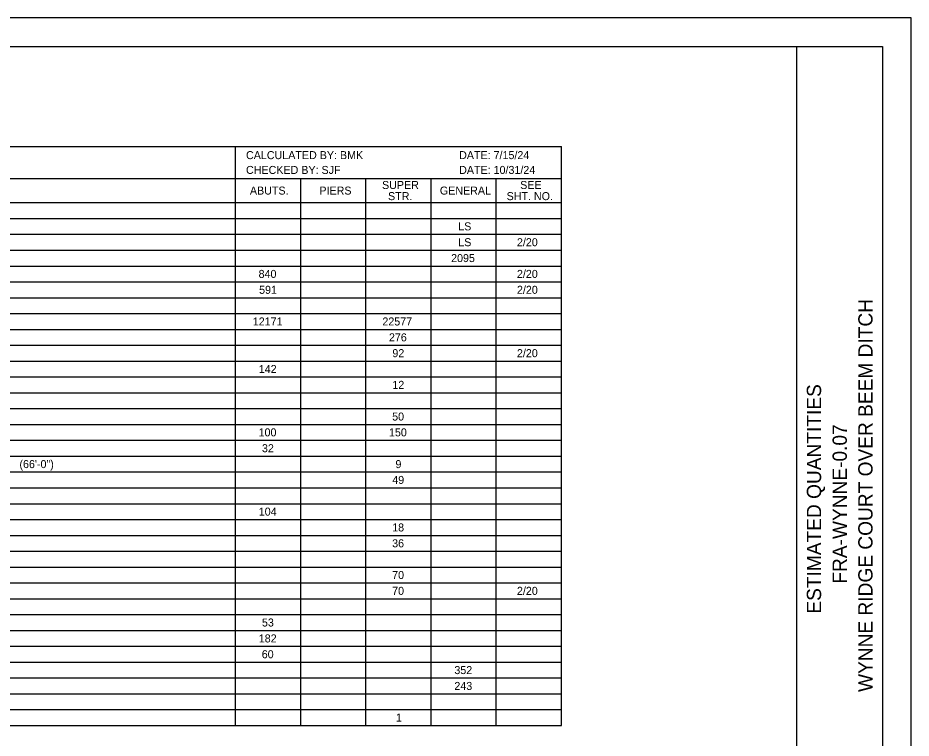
# Model space of a CAD drawing. Extents: x 0 to 34, y 0 to 22.
# Drawn here: x 18.37 to 34, y 9.41 to 22 of the extents above; entities that cross this region are included whole.
import ezdxf

# ---------------------------------------------------------------- set-up
doc = ezdxf.new("R2010")
doc.units = 0
for name, color, linetype in [('BR_P_Gen_Text', 7, 'Continuous'), ('SH_Border', 7, 'Continuous'), ('SH_Cut_Line', 7, 'Continuous'), ('SH_Data', 7, 'Continuous')]:
    doc.layers.add(name, color=color, linetype=linetype)

msp = doc.modelspace()

# ---------------------------------------------------------------- linework, layer by layer
at = {"layer": 'BR_P_Gen_Text'}
for p, q in [((5.618, 19.75), (27.882, 19.75)), ((22.177, 18.492), (22.177, 19.75)), ((27.882, 18.492), (27.882, 19.75)), ((5.618, 19.19), (27.882, 19.19)), ((23.318, 18.492), (23.318, 19.19)), ((24.459, 18.77), (24.459, 19.19)), ((25.6, 18.492), (25.6, 19.19)), ((26.741, 18.492), (26.741, 19.19)), ((5.618, 18.77), (27.882, 18.77)), ((10.182, 18.77), (24.459, 18.77)), ((24.459, 18.77), (25.6, 18.77)), ((24.459, 18.492), (24.459, 18.77)), ((25.6, 18.77), (27.882, 18.77)), ((5.618, 18.492), (27.882, 18.492)), ((5.618, 18.492), (27.882, 18.492)), ((22.177, 9.625), (22.177, 18.492)), ((23.318, 9.625), (23.318, 18.492)), ((24.459, 9.625), (24.459, 18.492)), ((25.6, 9.625), (25.6, 18.492)), ((26.741, 9.625), (26.741, 18.492)), ((27.882, 9.625), (27.882, 18.492)), ((5.618, 18.215), (27.882, 18.215)), ((5.618, 17.938), (27.882, 17.938)), ((5.618, 17.661), (27.882, 17.661)), ((5.618, 17.384), (27.882, 17.384)), ((5.618, 17.107), (27.882, 17.107)), ((5.618, 16.83), (27.882, 16.83)), ((5.618, 16.553), (27.882, 16.553)), ((5.618, 16.276), (27.882, 16.276)), ((5.618, 15.999), (27.882, 15.999)), ((5.618, 15.721), (27.882, 15.721)), ((5.618, 15.444), (27.882, 15.444)), ((5.618, 15.167), (27.882, 15.167)), ((5.618, 14.89), (27.882, 14.89)), ((5.618, 14.613), (27.882, 14.613)), ((5.618, 14.336), (27.882, 14.336)), ((5.618, 14.059), (27.882, 14.059)), ((5.618, 13.782), (27.882, 13.782)), ((5.618, 13.505), (27.882, 13.505)), ((5.618, 13.228), (27.882, 13.228)), ((5.618, 12.951), (27.882, 12.951)), ((5.618, 12.673), (27.882, 12.673)), ((5.618, 12.396), (27.882, 12.396)), ((5.618, 12.119), (27.882, 12.119)), ((5.618, 11.842), (27.882, 11.842)), ((5.618, 11.565), (27.882, 11.565)), ((5.618, 11.288), (27.882, 11.288)), ((5.618, 11.011), (27.882, 11.011)), ((5.618, 10.734), (27.882, 10.734)), ((5.618, 10.457), (27.882, 10.457)), ((5.618, 10.18), (27.882, 10.18)), ((5.618, 9.903), (27.882, 9.903)), ((5.618, 9.625), (27.882, 9.625))]:
    msp.add_line(p, q, dxfattribs=at)
at = {"layer": 'SH_Border'}
msp.add_line((32, 0.5), (32, 21.5), dxfattribs=at)
msp.add_lwpolyline([(1.5, 21.5), (33.5, 21.5), (33.5, 0.5), (1.5, 0.5)], close=True, dxfattribs=at)
at = {"layer": 'SH_Cut_Line'}
msp.add_lwpolyline([(0, 0), (34, 0), (34, 22), (0, 22)], close=True, dxfattribs=at)

# ---------------------------------------------------------------- texts
at = {"layer": 'BR_P_Gen_Text'}
for s, p in [('CALCULATED BY: BMK', (22.361, 19.53)), ('DATE: 7/15/24', (26.09, 19.53)), ('CHECKED BY: SJF', (22.361, 19.271)), ('DATE: 10/31/24', (26.09, 19.271)), ('SUPER', (24.741, 19.008)), ('SEE', (27.159, 19.008)), ('ABUTS.', (22.429, 18.91)), ('PIERS', (23.645, 18.91)), ('STR.', (24.846, 18.813)), ('GENERAL', (25.753, 18.91)), ('SHT. NO.', (26.921, 18.813)), ('LS', (26.075, 18.284)), ('LS', (26.075, 18.007)), ('2/20', (27.102, 18.007)), ('2095', (25.95, 17.73)), ('840', (22.581, 17.453)), ('2/20', (27.102, 17.453)), ('591', (22.59, 17.175)), ('2/20', (27.102, 17.175)), ('12171', (22.479, 16.621)), ('22577', (24.747, 16.621)), ('276', (24.862, 16.344)), ('92', (24.922, 16.067)), ('2/20', (27.102, 16.067)), ('142', (22.584, 15.79)), ('12', (24.922, 15.513)), ('50', (24.918, 14.959)), ('100', (22.581, 14.682)), ('150', (24.863, 14.682)), ('32', (22.64, 14.405)), (' (66\'-0")', (18.344, 14.127)), ('9', (24.976, 14.127)), ('49', (24.92, 13.85)), ('104', (22.584, 13.296)), ('18', (24.919, 13.019)), ('36', (24.918, 12.742)), ('70', (24.918, 12.188)), ('70', (24.918, 11.911)), ('2/20', (27.102, 11.911)), ('53', (22.64, 11.357)), ('182', (22.584, 11.079)), ('60', (22.636, 10.802)), ('352', (26.007, 10.525)), ('243', (26.007, 10.248)), ('1', (24.984, 9.694))]:
    msp.add_text(s, height=0.14, dxfattribs=at).set_placement(p)
at = {"layer": 'SH_Data'}
for s, p in [('WYNNE RIDGE COURT OVER BEEM DITCH', (33.325, 10.212)), ('ESTIMATED QUANTITIES', (32.425, 11.582)), ('FRA-WYNNE-0.07', (32.875, 12.106))]:
    msp.add_text(s, height=0.25, rotation=90, dxfattribs=at).set_placement(p)

doc.saveas('drawing.dxf')
